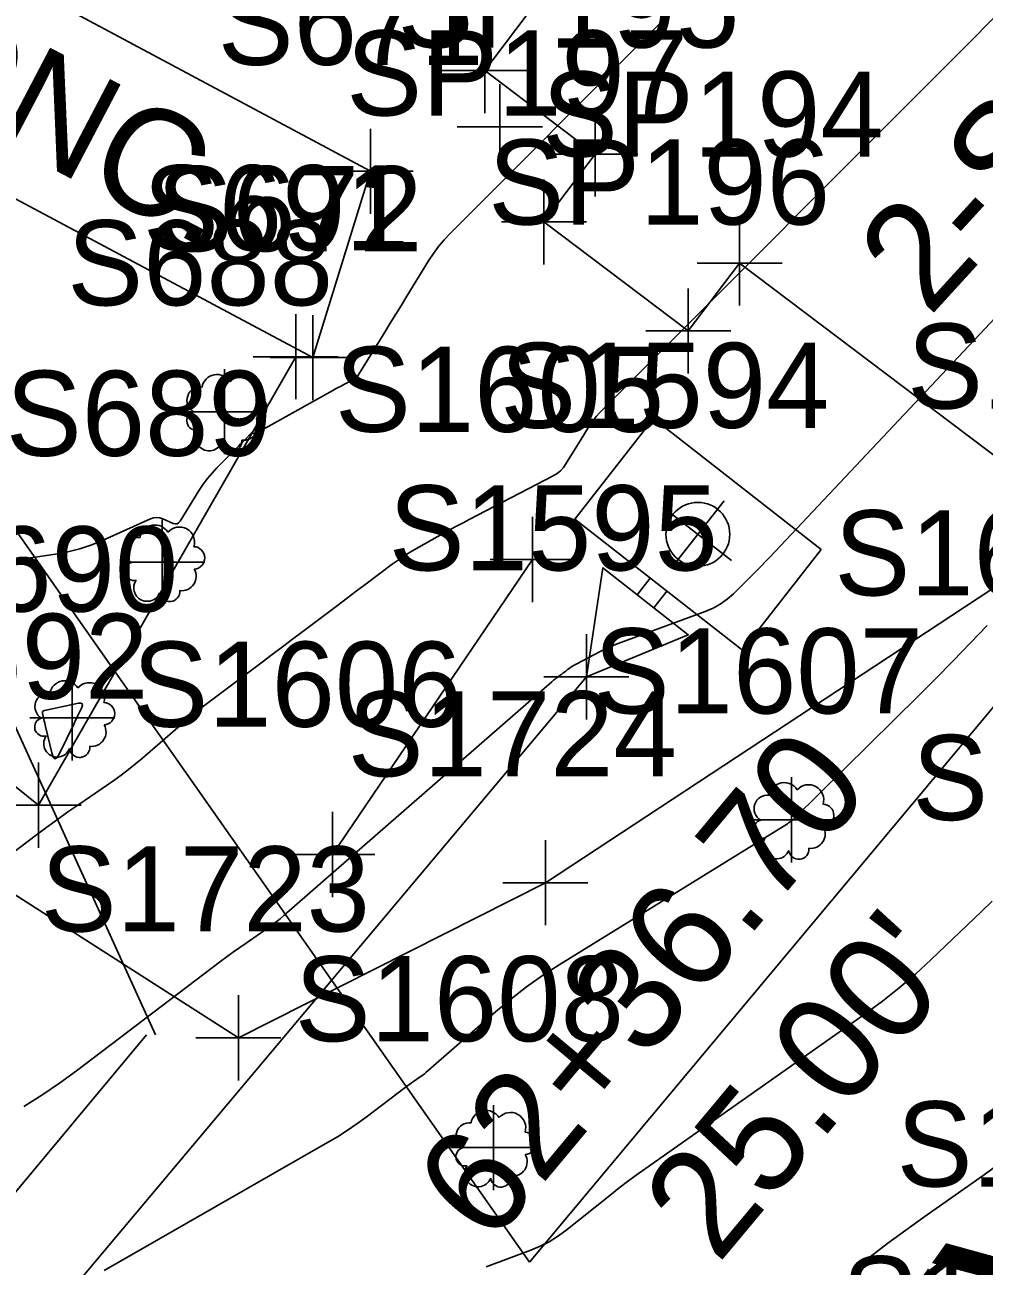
# Model space of a CAD drawing. Extents: x 816928 to 825690, y 436959 to 448212.
# Drawn here: x 819306 to 819351.1, y 445531.4 to 445589.7 of the extents above; entities that cross this region are included whole.
import ezdxf

# ---------------------------------------------------------------- set-up
doc = ezdxf.new("R2010")
doc.units = 0
for name, color, linetype in [('SURVEY - CONTOURS - Index with Text', 7, 'Continuous'), ('SURVEY - CONTOURS - Intermediate with optional Text', 7, 'Continuous'), ('SURVEY - DTM - Spot Points - Point Numbers', 7, 'Continuous'), ('SURVEY - NON-TRANSPORTATION - Buildings', 7, 'Continuous'), ('SURVEY - NON-TRANSPORTATION - Buildings - Points - Locators', 7, 'Continuous'), ('SURVEY - NON-TRANSPORTATION - Buildings - Points - Numbers', 7, 'Continuous'), ('SURVEY - NON-TRANSPORTATION - Buildings Text', 7, 'Continuous'), ('SURVEY - NON-TRANSPORTATION - Features', 7, 'Continuous'), ('SURVEY - NON-TRANSPORTATION - Features - Points - Locators', 7, 'Continuous'), ('SURVEY - NON-TRANSPORTATION - Features - Points - Numbers', 7, 'Continuous'), ('SURVEY - PROPERTY - Owners', 7, 'Continuous'), ('SURVEY - PROPERTY - Parcels', 7, 'Continuous'), ('SURVEY - PROPERTY - ROW Lines', 7, 'Continuous'), ('SURVEY - PROPERTY - ROW Lines Text', 7, 'Continuous'), ('SURVEY - PROPERTY - Station and Offset Flags', 7, 'Continuous'), ('SURVEY - TRANSPORTATION - Features', 7, 'Continuous'), ('SURVEY - TRANSPORTATION - Features - Points - Locators', 7, 'Continuous'), ('SURVEY - TRANSPORTATION - Features - Points - Numbers', 7, 'Continuous'), ('SURVEY - TRANSPORTATION - Features Text', 7, 'Continuous'), ('SURVEY - UTILITIES - Gas - Points - Locators', 7, 'Continuous'), ('SURVEY - UTILITIES - Gas - Points - Numbers', 7, 'Continuous'), ('SURVEY - UTILITIES - Gas with Text', 7, 'Continuous'), ('SURVEY - VEGETATION - Features - Points - Locators', 7, 'Continuous'), ('SURVEY - VEGETATION - Features - Points - Numbers', 7, 'Continuous'), ('SURVEY - VEGETATION - Features with Text', 7, 'Continuous')]:
    doc.layers.add(name, color=color, linetype=linetype)

msp = doc.modelspace()

# ---------------------------------------------------------------- linework, layer by layer
at = {"layer": 'SURVEY - CONTOURS - Index with Text'}
for points in [[(819297.154, 445563.334), (819307.461, 445564.855), (819308.039, 445564.96), (819308.605, 445565.105), (819309.16, 445565.289), (819309.704, 445565.512), (819311.919, 445566.513), (819312.066, 445566.562), (819312.213, 445566.579), (819312.36, 445566.562), (819312.506, 445566.512), (819312.986, 445566.295), (819313.084, 445566.267), (819313.17, 445566.273), (819313.246, 445566.316), (819313.311, 445566.394), (819314.212, 445567.849), (819314.398, 445568.131), (819314.598, 445568.401), (819314.814, 445568.659), (819315.045, 445568.905), (819315.989, 445569.858), (819316.073, 445569.943), (819316.157, 445570.027), (819316.241, 445570.112), (819316.325, 445570.197), (819316.69, 445570.564), (819316.703, 445570.574), (819316.715, 445570.577), (819316.726, 445570.571), (819316.737, 445570.558), (819316.768, 445570.502), (819316.775, 445570.493), (819316.784, 445570.488), (819316.794, 445570.487), (819316.806, 445570.492), (819320.488, 445572.541), (819320.616, 445572.612), (819320.745, 445572.682), (819320.875, 445572.751), (819321.004, 445572.819), (819321.429, 445573.04), (819321.515, 445573.093), (819321.592, 445573.155), (819321.66, 445573.227), (819321.718, 445573.31), (819322.93, 445575.282), (819323.189, 445575.704), (819323.449, 445576.127), (819323.708, 445576.549), (819323.968, 445576.972), (819324.985, 445578.627), (819325.212, 445578.974), (819325.458, 445579.306), (819325.724, 445579.623), (819326.008, 445579.925), (819335.434, 445589.369), (819337.452, 445591.395)], [(819344.922, 445531.189), (819345.742, 445531.832), (819346.57, 445532.463), (819347.408, 445533.082), (819348.255, 445533.688), (819351.038, 445535.647), (819351.626, 445536.078)]]:
    msp.add_lwpolyline(points, dxfattribs=at)
at = {"layer": 'SURVEY - CONTOURS - Intermediate with optional Text'}
for points in [[(819292.549, 445541.022), (819306.561, 445551.651), (819307.051, 445552.019), (819307.546, 445552.38), (819308.045, 445552.736), (819308.548, 445553.085), (819310.199, 445554.217), (819310.549, 445554.465), (819310.891, 445554.722), (819311.225, 445554.99), (819311.552, 445555.267), (819313.204, 445556.709), (819313.561, 445557.015), (819313.923, 445557.314), (819314.291, 445557.606), (819314.664, 445557.892), (819317.163, 445559.773), (819317.642, 445560.134), (819318.121, 445560.494), (819318.6, 445560.855), (819319.08, 445561.216), (819320.645, 445562.394), (819320.981, 445562.646), (819321.316, 445562.899), (819321.652, 445563.151), (819321.987, 445563.404), (819323.273, 445564.372), (819323.552, 445564.574), (819323.837, 445564.766), (819324.129, 445564.949), (819324.427, 445565.122), (819325.754, 445565.86), (819326.039, 445566.017), (819326.325, 445566.173), (819326.612, 445566.326), (819326.9, 445566.477), (819330.845, 445568.532), (819331.022, 445568.64), (819331.18, 445568.768), (819331.32, 445568.917), (819331.44, 445569.087), (819331.8, 445569.674), (819331.878, 445569.8), (819331.955, 445569.926), (819332.032, 445570.051), (819332.11, 445570.177), (819332.554, 445570.901), (819332.654, 445571.053), (819332.761, 445571.198), (819332.878, 445571.337), (819333.002, 445571.469), (819350.633, 445589.134), (819351.909, 445590.422)], [(819305.976, 445538.884), (819306.817, 445539.421), (819307.64, 445539.984), (819308.445, 445540.575), (819315.228, 445545.72), (819315.52, 445545.939), (819315.815, 445546.155), (819316.113, 445546.367), (819316.413, 445546.575), (819317.397, 445547.251), (819317.606, 445547.398), (819317.81, 445547.552), (819318.01, 445547.711), (819318.205, 445547.876), (819330.78, 445558.854), (819330.829, 445558.897), (819330.879, 445558.938), (819330.93, 445558.979), (819330.982, 445559.018), (819331.152, 445559.146), (819331.189, 445559.174), (819331.225, 445559.201), (819331.262, 445559.229), (819331.298, 445559.256), (819331.431, 445559.357), (819331.46, 445559.378), (819331.489, 445559.4), (819331.517, 445559.421), (819331.546, 445559.443), (819331.651, 445559.521), (819331.673, 445559.538), (819331.697, 445559.554), (819331.72, 445559.569), (819331.745, 445559.583), (819331.855, 445559.644), (819331.878, 445559.657), (819331.902, 445559.67), (819331.926, 445559.682), (819331.949, 445559.695), (819333.049, 445560.267), (819333.286, 445560.386), (819333.526, 445560.497), (819333.771, 445560.6), (819334.018, 445560.696), (819337.989, 445562.152), (819338.352, 445562.308), (819338.693, 445562.499), (819339.011, 445562.726), (819339.306, 445562.988), (819340.234, 445563.905), (819340.432, 445564.102), (819340.629, 445564.301), (819340.823, 445564.502), (819341.015, 445564.705), (819356.429, 445581.079)], [(819309.745, 445531.18), (819320.243, 445537.195), (819320.711, 445537.473), (819321.169, 445537.766), (819321.618, 445538.073), (819322.057, 445538.395), (819323.895, 445539.789), (819323.989, 445539.86), (819324.085, 445539.93), (819324.181, 445539.998), (819324.278, 445540.066), (819324.596, 445540.284), (819324.663, 445540.332), (819324.729, 445540.381), (819324.794, 445540.433), (819324.857, 445540.486), (819328.132, 445543.346), (819328.846, 445543.943), (819329.582, 445544.51), (819330.34, 445545.046), (819331.121, 445545.551), (819341.851, 445552.183), (819341.876, 445552.199), (819341.9, 445552.215), (819341.924, 445552.231), (819341.948, 445552.247), (819342.052, 445552.32), (819342.055, 445552.323), (819342.059, 445552.326), (819342.062, 445552.329), (819342.066, 445552.332), (819342.077, 445552.342), (819342.079, 445552.345), (819342.082, 445552.347), (819342.084, 445552.349), (819342.086, 445552.352), (819342.137, 445552.401), (819342.148, 445552.411), (819342.159, 445552.422), (819342.17, 445552.433), (819342.181, 445552.443), (819348.015, 445558.205), (819348.83, 445559.018), (819349.638, 445559.838), (819350.439, 445560.666), (819351.232, 445561.501)], [(819307.284, 445555.512), (819306.992, 445556.75), (819306.972, 445556.834), (819306.952, 445556.918), (819306.932, 445557.002), (819306.912, 445557.086), (819306.848, 445557.36), (819306.843, 445557.413), (819306.856, 445557.454), (819306.888, 445557.484), (819306.938, 445557.503), (819308.545, 445557.841), (819308.656, 445557.85), (819308.719, 445557.821), (819308.732, 445557.754), (819308.696, 445557.648), (819308.499, 445557.239), (819308.457, 445557.152), (819308.415, 445557.064), (819308.372, 445556.977), (819308.33, 445556.889), (819307.646, 445555.473), (819307.535, 445555.291), (819307.437, 445555.237), (819307.354, 445555.311), (819307.284, 445555.512)], [(819327.695, 445531.361), (819329.789, 445532.138), (819330.229, 445532.321), (819330.65, 445532.537), (819331.052, 445532.786), (819331.435, 445533.068), (819333.503, 445534.717), (819333.948, 445535.067), (819334.399, 445535.41), (819334.855, 445535.747), (819335.315, 445536.076), (819345.504, 445543.251), (819346.312, 445543.843), (819347.097, 445544.464), (819347.858, 445545.115), (819348.596, 445545.794), (819350.965, 445548.061), (819351.473, 445548.547)]]:
    msp.add_lwpolyline(points, dxfattribs=at)
at = {"layer": 'SURVEY - NON-TRANSPORTATION - Buildings'}
msp.add_lwpolyline([(819327.63, 445587.571), (819345.111, 445610.711), (819378.623, 445585.395), (819361.143, 445562.255), (819339.599, 445578.53), (819337.188, 445575.338), (819330.406, 445580.462), (819332.817, 445583.653), (819327.63, 445587.571)], dxfattribs=at)
at = {"layer": 'SURVEY - NON-TRANSPORTATION - Buildings - Points - Locators'}
for p, q in [((819327.63, 445589.571), (819327.63, 445585.571)), ((819329.63, 445587.571), (819325.63, 445587.571)), ((819332.817, 445585.653), (819332.817, 445581.653)), ((819334.817, 445583.653), (819330.817, 445583.653)), ((819330.406, 445582.462), (819330.406, 445578.462)), ((819332.406, 445580.462), (819328.406, 445580.462)), ((819339.599, 445580.53), (819339.599, 445576.53)), ((819341.599, 445578.53), (819337.599, 445578.53)), ((819337.188, 445577.338), (819337.188, 445573.338)), ((819339.188, 445575.338), (819335.188, 445575.338))]:
    msp.add_line(p, q, dxfattribs=at)
at = {"layer": 'SURVEY - NON-TRANSPORTATION - Features'}
for p, q in [((819329.875, 445564.597), (819320.467, 445550.737)), ((819335.397, 445563.727), (819334.781, 445562.939)), ((819336.185, 445563.111), (819335.569, 445562.323))]:
    msp.add_line(p, q, dxfattribs=at)
for points in [[(819343.426, 445565.065), (819339.73, 445560.338), (819331.853, 445566.499), (819335.549, 445571.225), (819343.426, 445565.065)], [(819332.403, 445559.085), (819296.387, 445516.214), (819277.216, 445494.588), (819259.349, 445482.1), (819231.923, 445463.445)]]:
    msp.add_lwpolyline(points, dxfattribs=at)
msp.add_lwpolyline([(819332.403, 445559.086), (819333.167, 445564.202), (819337.184, 445561.06)], close=True, dxfattribs=at)
msp.add_circle((819337.639, 445565.782), 1.5, dxfattribs=at)
at = {"layer": 'SURVEY - NON-TRANSPORTATION - Features - Points - Locators'}
for p, q in [((819328.338, 445586.934), (819328.338, 445582.934)), ((819330.338, 445584.934), (819326.338, 445584.934)), ((819336.064, 445567.014), (819339.215, 445564.55)), ((819336.407, 445564.206), (819338.872, 445567.357)), ((819329.875, 445566.597), (819329.875, 445562.597)), ((819331.875, 445564.597), (819327.875, 445564.597)), ((819332.403, 445561.085), (819332.403, 445557.085)), ((819334.403, 445559.085), (819330.403, 445559.085)), ((819320.467, 445552.737), (819320.467, 445548.737)), ((819322.467, 445550.737), (819318.467, 445550.737))]:
    msp.add_line(p, q, dxfattribs=at)
at = {"layer": 'SURVEY - PROPERTY - Parcels'}
msp.add_arc((818575.983, 446182.091), 935, 320.141729, 329.321022, dxfattribs=at)
at = {"layer": 'SURVEY - PROPERTY - ROW Lines'}
msp.add_arc((818575.983, 446182.091), 935, 320.141729, 329.321022, dxfattribs=at)
msp.add_arc((818575.983, 446182.091), 935, 320.141729, 329.321022, dxfattribs=at)
at = {"layer": 'SURVEY - PROPERTY - ROW Lines Text'}
msp.add_line((819311.729, 445542.263), (819265.421, 445486.797), dxfattribs=at)
msp.add_lwpolyline([(819312.156, 445542.263), (819293.691, 445582.824)], dxfattribs=at)
at = {"layer": 'SURVEY - PROPERTY - Station and Offset Flags'}
msp.add_line((819354.275, 445560.965), (819329.733, 445531.57), dxfattribs=at)
msp.add_lwpolyline([(819329.733, 445531.57), (819293.719, 445582.858)], dxfattribs=at)
at = {"layer": 'SURVEY - TRANSPORTATION - Features'}
for points in [[(819290.371, 445604.569), (819297.011, 445596.352), (819322.259, 445582.842), (819319.545, 445574.083), (819291.995, 445588.779), (819280.694, 445592.472)], [(819318.745, 445574.129), (819306.664, 445553.05), (819293.667, 445563.515), (819294.599, 445567.059), (819271.707, 445581.193)]]:
    msp.add_lwpolyline(points, dxfattribs=at)
at = {"layer": 'SURVEY - TRANSPORTATION - Features - Points - Locators'}
for p, q in [((819322.259, 445584.842), (819322.259, 445580.842)), ((819324.259, 445582.842), (819320.259, 445582.842)), ((819318.745, 445576.129), (819318.745, 445572.129)), ((819319.545, 445576.083), (819319.545, 445572.083)), ((819320.745, 445574.129), (819316.745, 445574.129)), ((819321.545, 445574.083), (819317.545, 445574.083)), ((819306.664, 445555.05), (819306.664, 445551.05)), ((819308.664, 445553.05), (819304.664, 445553.05))]:
    msp.add_line(p, q, dxfattribs=at)
at = {"layer": 'SURVEY - UTILITIES - Gas - Points - Locators'}
for p, q in [((819330.474, 445551.407), (819330.474, 445547.407)), ((819332.474, 445549.407), (819328.474, 445549.407)), ((819316.051, 445544.116), (819316.051, 445540.116)), ((819318.051, 445542.116), (819314.051, 445542.116))]:
    msp.add_line(p, q, dxfattribs=at)
at = {"layer": 'SURVEY - UTILITIES - Gas with Text'}
msp.add_lwpolyline([(819255.402, 445587.957), (819296.534, 445554.619), (819316.051, 445542.116), (819330.474, 445549.407), (819356.758, 445566.69)], dxfattribs=at)
at = {"layer": 'SURVEY - VEGETATION - Features - Points - Locators'}
for p, q in [((819315.393, 445573.541), (819315.393, 445569.541)), ((819317.393, 445571.541), (819313.393, 445571.541)), ((819312.478, 445566.469), (819312.478, 445562.469)), ((819314.478, 445564.469), (819310.478, 445564.469)), ((819308.246, 445559.152), (819308.246, 445555.152)), ((819310.246, 445557.152), (819306.246, 445557.152)), ((819342.035, 445554.362), (819342.035, 445550.362)), ((819344.035, 445552.362), (819340.035, 445552.362)), ((819328.032, 445538.958), (819328.032, 445534.958)), ((819330.032, 445536.958), (819326.032, 445536.958))]:
    msp.add_line(p, q, dxfattribs=at)
at = {"layer": 'SURVEY - VEGETATION - Features with Text'}
for centre in [(819315.41, 445571.546), (819312.495, 445564.475), (819308.263, 445557.157), (819342.053, 445552.368), (819328.05, 445536.963)]:
    msp.add_circle(centre, 0.022, dxfattribs=at)
for centre, radius, start, end in [((819315.05, 445572.572), 0.719, 31.96825, 169.49248), ((819314.267, 445572.077), 0.631, 82.91551, 239.70443), ((819316.196, 445572.481), 0.714, 342.86408, 138.70256), ((819316.861, 445571.744), 0.527, 273.11698, 88.11726), ((819314.061, 445571.114), 0.433, 105.03166, 283.77731), ((819316.301, 445570.881), 0.679, 262.95807, 29.80374), ((819314.68, 445570.333), 0.629, 145.05235, 338.47204), ((819315.74, 445570.166), 0.479, 187.67102, 4.99016), ((819312.135, 445565.5), 0.719, 31.96825, 169.49248), ((819313.281, 445565.409), 0.714, 342.86408, 138.70256), ((819311.352, 445565.005), 0.631, 82.91551, 239.70443), ((819313.946, 445564.673), 0.527, 273.11698, 88.11726), ((819311.146, 445564.042), 0.433, 105.03166, 283.77731), ((819313.386, 445563.809), 0.679, 262.95807, 29.80374), ((819311.765, 445563.261), 0.629, 145.05235, 338.47204), ((819312.825, 445563.094), 0.479, 187.67102, 4.99016), ((819307.904, 445558.182), 0.719, 31.96825, 169.49248), ((819309.05, 445558.091), 0.714, 342.86408, 138.70256), ((819307.121, 445557.687), 0.631, 82.91551, 239.70443), ((819309.715, 445557.355), 0.527, 273.11698, 88.11726), ((819306.915, 445556.724), 0.433, 105.03166, 283.77731), ((819309.155, 445556.492), 0.679, 262.95807, 29.80374), ((819307.534, 445555.943), 0.629, 145.05235, 338.47204), ((819308.594, 445555.776), 0.479, 187.67102, 4.99016), ((819341.693, 445553.393), 0.719, 31.96825, 169.49248), ((819340.91, 445552.898), 0.631, 82.91551, 239.70443), ((819342.839, 445553.302), 0.714, 342.86408, 138.70256), ((819343.504, 445552.566), 0.527, 273.11698, 88.11726), ((819340.704, 445551.935), 0.433, 105.03166, 283.77731), ((819342.944, 445551.702), 0.679, 262.95807, 29.80374), ((819341.323, 445551.154), 0.629, 145.05235, 338.47204), ((819342.383, 445550.987), 0.479, 187.67102, 4.99016), ((819327.69, 445537.989), 0.719, 31.96825, 169.49248), ((819328.836, 445537.898), 0.714, 342.86408, 138.70256), ((819326.907, 445537.494), 0.631, 82.91551, 239.70443), ((819329.501, 445537.161), 0.527, 273.11698, 88.11726), ((819326.701, 445536.531), 0.433, 105.03166, 283.77731), ((819328.941, 445536.298), 0.679, 262.95807, 29.80374), ((819327.32, 445535.75), 0.629, 145.05235, 338.47204), ((819328.38, 445535.583), 0.479, 187.67102, 4.99016)]:
    msp.add_arc(centre, radius, start, end, dxfattribs=at)

# ---------------------------------------------------------------- texts
at = {"layer": 'SURVEY - DTM - Spot Points - Point Numbers'}
msp.add_text('S1185', height=4, dxfattribs=at).set_placement((819347.707, 445552.353))
at = {"layer": 'SURVEY - NON-TRANSPORTATION - Buildings - Points - Numbers'}
for s, p in [('SP195', (819323.529, 445588.653)), ('SP197', (819321.118, 445585.462)), ('SP194', (819330.311, 445583.53)), ('SP196', (819327.79, 445580.338))]:
    msp.add_text(s, height=4, dxfattribs=at).set_placement(p)
at = {"layer": 'SURVEY - NON-TRANSPORTATION - Buildings Text'}
msp.add_text('2-S-F', height=5, rotation=47.63058, dxfattribs=at).set_placement((819348.506, 445575.953))
at = {"layer": 'SURVEY - NON-TRANSPORTATION - Features - Points - Numbers'}
for s, p in [('S1605', (819320.587, 445570.597)), ('S1594', (819328.352, 445570.782)), ('S1595', (819323.115, 445564.085)), ('S1606', (819311.069, 445556.737))]:
    msp.add_text(s, height=4, dxfattribs=at).set_placement(p)
at = {"layer": 'SURVEY - PROPERTY - Owners'}
for s, p in [('RUTH B. WHITE ETVIR ', (819294.492, 445439.981)), ('CURTISS L. WHITE ETUX', (819318.563, 445422.927))]:
    msp.add_text(s, height=8.75, rotation=54.68153, dxfattribs=at).set_placement(p)
at = {"layer": 'SURVEY - PROPERTY - Station and Offset Flags'}
for s, p in [(' 62+36.70', (819326.692, 445530.853)), ("25.00'", (819338.58, 445531.439))]:
    msp.add_text(s, height=5, rotation=50.14173, dxfattribs=at).set_placement(p)
at = {"layer": 'SURVEY - TRANSPORTATION - Features - Points - Numbers'}
for s, p in [('S671', (819315.081, 445587.842)), ('S691', (819311.566, 445579.129)), ('S672', (819312.209, 445579.083)), ('S692', (819299.328, 445558.05))]:
    msp.add_text(s, height=4, dxfattribs=at).set_placement(p)
at = {"layer": 'SURVEY - TRANSPORTATION - Features Text'}
msp.add_text('CONC.', height=5, rotation=332.34373, dxfattribs=at).set_placement((819295.517, 445589.133))
at = {"layer": 'SURVEY - UTILITIES - Gas - Points - Numbers'}
for s, p in [('S1603', (819347.47, 445571.69)), ('S1724', (819321.186, 445554.407)), ('S1723', (819306.763, 445547.116))]:
    msp.add_text(s, height=4, dxfattribs=at).set_placement(p)
at = {"layer": 'SURVEY - VEGETATION - Features - Points - Numbers'}
for s, p in [('S688', (819308.01, 445576.541)), ('S689', (819305.126, 445569.469)), ('S1610', (819344.051, 445562.91)), ('S690', (819300.737, 445562.152)), ('S1607', (819332.748, 445557.362)), ('S1608', (819318.698, 445541.958)), ('S1588', (819346.978, 445535.132)), ('S1587', (819344.396, 445527.852))]:
    msp.add_text(s, height=4, dxfattribs=at).set_placement(p)

doc.saveas('drawing.dxf')
